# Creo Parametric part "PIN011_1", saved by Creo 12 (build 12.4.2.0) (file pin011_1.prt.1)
Units: Custom; MM, KILOGRAM, SECS

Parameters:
  PTC_WM_ITERATION = "0"
  PTC_WM_VERSION = "-.0"
  PTC_WM_LIFECYCLE_STATE = "In Work"
  PTC_WM_LIFECYCLE = "MO_CADDocument"
  PTC_WM_CREATED_BY = "Maximilian Roepper (Z0017RMS: MO)"
  PTC_WM_CREATED_ON = "18-Sep-26 11:36:42 AM"
  PTC_WM_MODIFIED_BY = "Maximilian Roepper (Z0017RMS: MO)"
  PTC_WM_MODIFIED_ON = "18-Sep-26 11:36:46 AM"
  PDMLINKNUMBER = "PDM000071454829"
  PTC_WM_NAME = "pin011_1.prt"
  PTC_WM_NUMBER = "PDM000071454829"

Other parameters: WEIGHT, WEIGHT_FACTOR, WEIGHT_ADD, _MASS_TEMP, _DIFF_TEMP, MC_ERRORS, SUPPLIER

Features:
  1. coordinate system
  2. datum plane "PRT_YZ"
  3. datum plane "PRT_XY"
  4. datum plane "PRT_XZ"
  5. coordinate system
  6. datum axis
  7. datum axis
  8. datum axis
  9. coordinate system
  10. imported feature

Other named items: PRT, SIEMENS_MO, DRW_VIEW_ORG, PRT_X, PRT_Y, PRT_Z, CS0, ROUGH_GROB

Layers: 00_STD_CSYS-KSYS, 01_STD_PLANES-EBENEN, 02_STD_AXES-ACHSEN, 03_STD_CSYS-KSYS, 24_IMPORT_FEAT-IMPORT_KE

Surfaces: 14 plane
